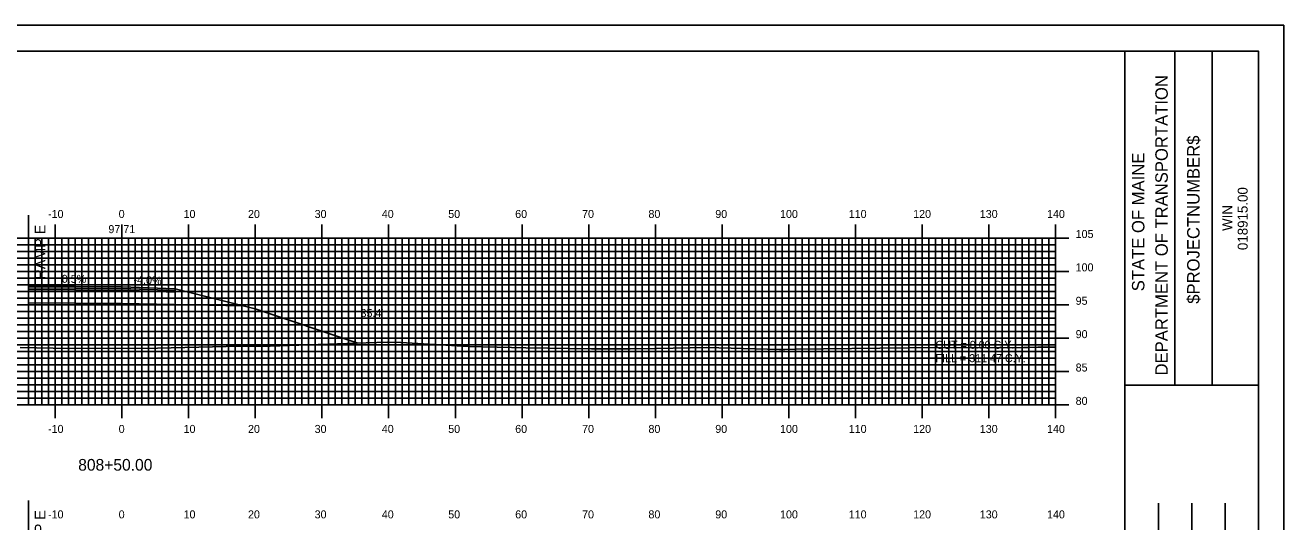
# Model space of a CAD drawing. Extents: x 1272 to 1616, y -1658 to -1438.
# Drawn here: x 1423.7 to 1612.4, y -1512.1 to -1437.7 of the extents above; entities that cross this region are included whole.
import ezdxf

# ---------------------------------------------------------------- set-up
doc = ezdxf.new("R2010")
doc.units = 0
for name, color, linetype in [('ANNOTATION', 7, 'Continuous'), ('BORDER', 7, 'Continuous'), ('D_Roadway_Centerline_Text', 7, 'Continuous'), ('D_Roadway_Edge_Shoulder', 7, 'Continuous'), ('D_Roadway_Edge_TW', 7, 'Continuous'), ('D_Roadway_Pavement', 7, 'Continuous'), ('D_Roadway_SlopeLines', 7, 'Continuous'), ('D_Roadway_SubGrade', 7, 'Continuous'), ('D_Text_Standard', 7, 'Continuous'), ('H_V ANNOTATION', 7, 'Continuous'), ('MAJOR', 7, 'Continuous'), ('MINOR', 7, 'Continuous'), ('PLOT BOUNDARY', 7, 'Continuous'), ('S_Roadway_Centerline', 7, 'Continuous')]:
    doc.layers.add(name, color=color, linetype=linetype)

msp = doc.modelspace()

# ---------------------------------------------------------------- linework, layer by layer
at = {"layer": 'BORDER'}
for p, q in [((1588.56, -1651.6), (1588.56, -1441.6)), ((1596.02, -1491.61), (1596.02, -1441.61)), ((1601.61, -1491.61), (1601.61, -1441.61)), ((1588.56, -1491.62), (1608.56, -1491.62)), ((1593.56, -1526.6), (1593.56, -1509.3)), ((1598.56, -1526.6), (1598.56, -1509.3)), ((1603.56, -1526.6), (1603.56, -1509.3))]:
    msp.add_line(p, q, dxfattribs=at)
msp.add_lwpolyline([(1288.56, -1651.6), (1608.56, -1651.6), (1608.56, -1441.6), (1288.56, -1441.6)], close=True, dxfattribs=at)
at = {"layer": 'D_Roadway_Edge_Shoulder'}
for points in [[(1438.16, -1476.89), (1446.16, -1477.21), (1446.16, -1477.46), (1438.16, -1477.14)], [(1438.16, -1477.14), (1446.16, -1477.46), (1446.16, -1477.71), (1438.16, -1477.39)]]:
    msp.add_lwpolyline(points, close=True, dxfattribs=at)
at = {"layer": 'D_Roadway_Edge_TW'}
msp.add_lwpolyline([(1424.16, -1476.83), (1438.16, -1476.89), (1438.16, -1477.14), (1424.16, -1477.08)], close=True, dxfattribs=at)
at = {"layer": 'D_Roadway_Pavement'}
msp.add_lwpolyline([(1424.16, -1477.08), (1438.16, -1477.14), (1438.16, -1477.39), (1424.16, -1477.33)], close=True, dxfattribs=at)
msp.add_lwpolyline([(1438.16, -1477.14), (1438.16, -1477.39)], dxfattribs=at)
msp.add_lwpolyline([(1438.16, -1477.14), (1438.16, -1477.39)], dxfattribs=at)
msp.add_lwpolyline([(1438.16, -1477.14), (1438.16, -1477.39)], dxfattribs=at)
at = {"layer": 'D_Roadway_SlopeLines'}
msp.add_lwpolyline([(1446.16, -1477.21), (1458.16, -1480.21), (1473.54, -1485.34)], dxfattribs=at)
at = {"layer": 'D_Roadway_SubGrade'}
for p, q in [((1424.16, -1466.19), (1424.16, -1479.33)), ((1424.16, -1508.94), (1424.16, -1522.08))]:
    msp.add_line(p, q, dxfattribs=at)
for points in [[(1424.16, -1477.33), (1438.16, -1477.39), (1438.16, -1479.39), (1424.16, -1479.33)], [(1438.16, -1477.39), (1438.16, -1477.14), (1446.16, -1477.46), (1446.16, -1477.21), (1456.33, -1479.75), (1438.16, -1479.39)]]:
    msp.add_lwpolyline(points, close=True, dxfattribs=at)
at = {"layer": 'MAJOR'}
for p, q in [((1428.16, -1467.6), (1428.16, -1469.6)), ((1438.16, -1467.6), (1438.16, -1469.6)), ((1448.16, -1467.6), (1448.16, -1469.6)), ((1458.16, -1467.6), (1458.16, -1469.6)), ((1468.16, -1467.6), (1468.16, -1469.6)), ((1478.16, -1467.6), (1478.16, -1469.6)), ((1488.16, -1467.6), (1488.16, -1469.6)), ((1498.16, -1467.6), (1498.16, -1469.6)), ((1508.16, -1467.6), (1508.16, -1469.6)), ((1518.16, -1467.6), (1518.16, -1469.6)), ((1528.16, -1467.6), (1528.16, -1469.6)), ((1538.16, -1467.6), (1538.16, -1469.6)), ((1548.16, -1467.6), (1548.16, -1469.6)), ((1558.16, -1467.6), (1558.16, -1469.6)), ((1568.16, -1467.6), (1568.16, -1469.6)), ((1578.16, -1467.6), (1578.16, -1469.6)), ((1298.16, -1469.6), (1578.16, -1469.6)), ((1298.16, -1469.6), (1578.16, -1469.6)), ((1428.16, -1494.6), (1428.16, -1469.6)), ((1438.16, -1494.6), (1438.16, -1469.6)), ((1448.16, -1494.6), (1448.16, -1469.6)), ((1458.16, -1494.6), (1458.16, -1469.6)), ((1468.16, -1494.6), (1468.16, -1469.6)), ((1478.16, -1494.6), (1478.16, -1469.6)), ((1488.16, -1494.6), (1488.16, -1469.6)), ((1498.16, -1494.6), (1498.16, -1469.6)), ((1508.16, -1494.6), (1508.16, -1469.6)), ((1518.16, -1494.6), (1518.16, -1469.6)), ((1528.16, -1494.6), (1528.16, -1469.6)), ((1538.16, -1494.6), (1538.16, -1469.6)), ((1548.16, -1494.6), (1548.16, -1469.6)), ((1558.16, -1494.6), (1558.16, -1469.6)), ((1568.16, -1494.6), (1568.16, -1469.6)), ((1580.16, -1469.6), (1576.16, -1469.6)), ((1578.16, -1494.6), (1578.16, -1469.6)), ((1578.16, -1494.6), (1578.16, -1469.6)), ((1298.16, -1474.6), (1578.16, -1474.6)), ((1580.16, -1474.6), (1576.16, -1474.6)), ((1298.16, -1479.6), (1578.16, -1479.6)), ((1580.16, -1479.6), (1576.16, -1479.6)), ((1298.16, -1484.6), (1578.16, -1484.6)), ((1580.16, -1484.6), (1576.16, -1484.6)), ((1298.16, -1489.6), (1578.16, -1489.6)), ((1580.16, -1489.6), (1576.16, -1489.6)), ((1298.16, -1494.6), (1578.16, -1494.6)), ((1298.16, -1494.6), (1578.16, -1494.6)), ((1428.16, -1496.61), (1428.16, -1494.6)), ((1438.16, -1496.61), (1438.16, -1494.6)), ((1448.16, -1496.61), (1448.16, -1494.6)), ((1458.16, -1496.61), (1458.16, -1494.6)), ((1468.16, -1496.61), (1468.16, -1494.6)), ((1478.16, -1496.61), (1478.16, -1494.6)), ((1488.16, -1496.61), (1488.16, -1494.6)), ((1498.16, -1496.61), (1498.16, -1494.6)), ((1508.16, -1496.61), (1508.16, -1494.6)), ((1518.16, -1496.61), (1518.16, -1494.6)), ((1528.16, -1496.61), (1528.16, -1494.6)), ((1538.16, -1496.61), (1538.16, -1494.6)), ((1548.16, -1496.61), (1548.16, -1494.6)), ((1558.16, -1496.61), (1558.16, -1494.6)), ((1568.16, -1496.61), (1568.16, -1494.6)), ((1580.16, -1494.6), (1576.16, -1494.6)), ((1578.16, -1496.61), (1578.16, -1494.6))]:
    msp.add_line(p, q, dxfattribs=at)
at = {"layer": 'MINOR'}
for p, q in [((1424.16, -1494.6), (1424.16, -1469.6)), ((1425.16, -1494.6), (1425.16, -1469.6)), ((1426.16, -1494.6), (1426.16, -1469.6)), ((1427.16, -1494.6), (1427.16, -1469.6)), ((1429.16, -1494.6), (1429.16, -1469.6)), ((1430.16, -1494.6), (1430.16, -1469.6)), ((1431.16, -1494.6), (1431.16, -1469.6)), ((1432.16, -1494.6), (1432.16, -1469.6)), ((1433.16, -1494.6), (1433.16, -1469.6)), ((1434.16, -1494.6), (1434.16, -1469.6)), ((1435.16, -1494.6), (1435.16, -1469.6)), ((1436.16, -1494.6), (1436.16, -1469.6)), ((1437.16, -1494.6), (1437.16, -1469.6)), ((1439.16, -1494.6), (1439.16, -1469.6)), ((1440.16, -1494.6), (1440.16, -1469.6)), ((1441.16, -1494.6), (1441.16, -1469.6)), ((1442.16, -1494.6), (1442.16, -1469.6)), ((1443.16, -1494.6), (1443.16, -1469.6)), ((1444.16, -1494.6), (1444.16, -1469.6)), ((1445.16, -1494.6), (1445.16, -1469.6)), ((1446.16, -1494.6), (1446.16, -1469.6)), ((1447.16, -1494.6), (1447.16, -1469.6)), ((1449.16, -1494.6), (1449.16, -1469.6)), ((1450.16, -1494.6), (1450.16, -1469.6)), ((1451.16, -1494.6), (1451.16, -1469.6)), ((1452.16, -1494.6), (1452.16, -1469.6)), ((1453.16, -1494.6), (1453.16, -1469.6)), ((1454.16, -1494.6), (1454.16, -1469.6)), ((1455.16, -1494.6), (1455.16, -1469.6)), ((1456.16, -1494.6), (1456.16, -1469.6)), ((1457.16, -1494.6), (1457.16, -1469.6)), ((1459.16, -1494.6), (1459.16, -1469.6)), ((1460.16, -1494.6), (1460.16, -1469.6)), ((1461.16, -1494.6), (1461.16, -1469.6)), ((1462.16, -1494.6), (1462.16, -1469.6)), ((1463.16, -1494.6), (1463.16, -1469.6)), ((1464.16, -1494.6), (1464.16, -1469.6)), ((1465.16, -1494.6), (1465.16, -1469.6)), ((1466.16, -1494.6), (1466.16, -1469.6)), ((1467.16, -1494.6), (1467.16, -1469.6)), ((1469.16, -1494.6), (1469.16, -1469.6)), ((1470.16, -1494.6), (1470.16, -1469.6)), ((1471.16, -1494.6), (1471.16, -1469.6)), ((1472.16, -1494.6), (1472.16, -1469.6)), ((1473.16, -1494.6), (1473.16, -1469.6)), ((1474.16, -1494.6), (1474.16, -1469.6)), ((1475.16, -1494.6), (1475.16, -1469.6)), ((1476.16, -1494.6), (1476.16, -1469.6)), ((1477.16, -1494.6), (1477.16, -1469.6)), ((1479.16, -1494.6), (1479.16, -1469.6)), ((1480.16, -1494.6), (1480.16, -1469.6)), ((1481.16, -1494.6), (1481.16, -1469.6)), ((1482.16, -1494.6), (1482.16, -1469.6)), ((1483.16, -1494.6), (1483.16, -1469.6)), ((1484.16, -1494.6), (1484.16, -1469.6)), ((1485.16, -1494.6), (1485.16, -1469.6)), ((1486.16, -1494.6), (1486.16, -1469.6)), ((1487.16, -1494.6), (1487.16, -1469.6)), ((1489.16, -1494.6), (1489.16, -1469.6)), ((1490.16, -1494.6), (1490.16, -1469.6)), ((1491.16, -1494.6), (1491.16, -1469.6)), ((1492.16, -1494.6), (1492.16, -1469.6)), ((1493.16, -1494.6), (1493.16, -1469.6)), ((1494.16, -1494.6), (1494.16, -1469.6)), ((1495.16, -1494.6), (1495.16, -1469.6)), ((1496.16, -1494.6), (1496.16, -1469.6)), ((1497.16, -1494.6), (1497.16, -1469.6)), ((1499.16, -1494.6), (1499.16, -1469.6)), ((1500.16, -1494.6), (1500.16, -1469.6)), ((1501.16, -1494.6), (1501.16, -1469.6)), ((1502.16, -1494.6), (1502.16, -1469.6)), ((1503.16, -1494.6), (1503.16, -1469.6)), ((1504.16, -1494.6), (1504.16, -1469.6)), ((1505.16, -1494.6), (1505.16, -1469.6)), ((1506.16, -1494.6), (1506.16, -1469.6)), ((1507.16, -1494.6), (1507.16, -1469.6)), ((1509.16, -1494.6), (1509.16, -1469.6)), ((1510.16, -1494.6), (1510.16, -1469.6)), ((1511.16, -1494.6), (1511.16, -1469.6)), ((1512.16, -1494.6), (1512.16, -1469.6)), ((1513.16, -1494.6), (1513.16, -1469.6)), ((1514.16, -1494.6), (1514.16, -1469.6)), ((1515.16, -1494.6), (1515.16, -1469.6)), ((1516.16, -1494.6), (1516.16, -1469.6)), ((1517.16, -1494.6), (1517.16, -1469.6)), ((1519.16, -1494.6), (1519.16, -1469.6)), ((1520.16, -1494.6), (1520.16, -1469.6)), ((1521.16, -1494.6), (1521.16, -1469.6)), ((1522.16, -1494.6), (1522.16, -1469.6)), ((1523.16, -1494.6), (1523.16, -1469.6)), ((1524.16, -1494.6), (1524.16, -1469.6)), ((1525.16, -1494.6), (1525.16, -1469.6)), ((1526.16, -1494.6), (1526.16, -1469.6)), ((1527.16, -1494.6), (1527.16, -1469.6)), ((1529.16, -1494.6), (1529.16, -1469.6)), ((1530.16, -1494.6), (1530.16, -1469.6)), ((1531.16, -1494.6), (1531.16, -1469.6)), ((1532.16, -1494.6), (1532.16, -1469.6)), ((1533.16, -1494.6), (1533.16, -1469.6)), ((1534.16, -1494.6), (1534.16, -1469.6)), ((1535.16, -1494.6), (1535.16, -1469.6)), ((1536.16, -1494.6), (1536.16, -1469.6)), ((1537.16, -1494.6), (1537.16, -1469.6)), ((1539.16, -1494.6), (1539.16, -1469.6)), ((1540.16, -1494.6), (1540.16, -1469.6)), ((1541.16, -1494.6), (1541.16, -1469.6)), ((1542.16, -1494.6), (1542.16, -1469.6)), ((1543.16, -1494.6), (1543.16, -1469.6)), ((1544.16, -1494.6), (1544.16, -1469.6)), ((1545.16, -1494.6), (1545.16, -1469.6)), ((1546.16, -1494.6), (1546.16, -1469.6)), ((1547.16, -1494.6), (1547.16, -1469.6)), ((1549.16, -1494.6), (1549.16, -1469.6)), ((1550.16, -1494.6), (1550.16, -1469.6)), ((1551.16, -1494.6), (1551.16, -1469.6)), ((1552.16, -1494.6), (1552.16, -1469.6)), ((1553.16, -1494.6), (1553.16, -1469.6)), ((1554.16, -1494.6), (1554.16, -1469.6)), ((1555.16, -1494.6), (1555.16, -1469.6)), ((1556.16, -1494.6), (1556.16, -1469.6)), ((1557.16, -1494.6), (1557.16, -1469.6)), ((1559.16, -1494.6), (1559.16, -1469.6)), ((1560.16, -1494.6), (1560.16, -1469.6)), ((1561.16, -1494.6), (1561.16, -1469.6)), ((1562.16, -1494.6), (1562.16, -1469.6)), ((1563.16, -1494.6), (1563.16, -1469.6)), ((1564.16, -1494.6), (1564.16, -1469.6)), ((1565.16, -1494.6), (1565.16, -1469.6)), ((1566.16, -1494.6), (1566.16, -1469.6)), ((1567.16, -1494.6), (1567.16, -1469.6)), ((1569.16, -1494.6), (1569.16, -1469.6)), ((1570.16, -1494.6), (1570.16, -1469.6)), ((1571.16, -1494.6), (1571.16, -1469.6)), ((1572.16, -1494.6), (1572.16, -1469.6)), ((1573.16, -1494.6), (1573.16, -1469.6)), ((1574.16, -1494.6), (1574.16, -1469.6)), ((1575.16, -1494.6), (1575.16, -1469.6)), ((1576.16, -1494.6), (1576.16, -1469.6)), ((1577.16, -1494.6), (1577.16, -1469.6)), ((1298.16, -1470.6), (1578.16, -1470.6)), ((1298.16, -1471.6), (1578.16, -1471.6)), ((1578.16, -1470.6), (1576.16, -1470.6)), ((1578.16, -1471.6), (1576.16, -1471.6)), ((1298.16, -1472.6), (1578.16, -1472.6)), ((1298.16, -1473.6), (1578.16, -1473.6)), ((1578.16, -1472.6), (1576.16, -1472.6)), ((1578.16, -1473.6), (1576.16, -1473.6)), ((1298.16, -1475.6), (1578.16, -1475.6)), ((1578.16, -1475.6), (1576.16, -1475.6)), ((1298.16, -1476.6), (1578.16, -1476.6)), ((1298.16, -1477.6), (1578.16, -1477.6)), ((1578.16, -1476.6), (1576.16, -1476.6)), ((1578.16, -1477.6), (1576.16, -1477.6)), ((1298.16, -1478.6), (1578.16, -1478.6)), ((1578.16, -1478.6), (1576.16, -1478.6)), ((1298.16, -1480.6), (1578.16, -1480.6)), ((1578.16, -1480.6), (1576.16, -1480.6)), ((1298.16, -1481.6), (1578.16, -1481.6)), ((1298.16, -1482.6), (1578.16, -1482.6)), ((1578.16, -1481.6), (1576.16, -1481.6)), ((1578.16, -1482.6), (1576.16, -1482.6)), ((1298.16, -1483.6), (1578.16, -1483.6)), ((1578.16, -1483.6), (1576.16, -1483.6)), ((1298.16, -1485.6), (1578.16, -1485.6)), ((1298.16, -1486.6), (1578.16, -1486.6)), ((1578.16, -1485.6), (1576.16, -1485.6)), ((1578.16, -1486.6), (1576.16, -1486.6)), ((1298.16, -1487.6), (1578.16, -1487.6)), ((1298.16, -1488.6), (1578.16, -1488.6)), ((1578.16, -1487.6), (1576.16, -1487.6)), ((1578.16, -1488.6), (1576.16, -1488.6)), ((1298.16, -1490.6), (1578.16, -1490.6)), ((1578.16, -1490.6), (1576.16, -1490.6)), ((1298.16, -1491.6), (1578.16, -1491.6)), ((1298.16, -1492.6), (1578.16, -1492.6)), ((1578.16, -1491.6), (1576.16, -1491.6)), ((1578.16, -1492.6), (1576.16, -1492.6)), ((1298.16, -1493.6), (1578.16, -1493.6)), ((1578.16, -1493.6), (1576.16, -1493.6))]:
    msp.add_line(p, q, dxfattribs=at)
at = {"layer": 'PLOT BOUNDARY'}
msp.add_lwpolyline([(1272.37, -1657.72), (1612.37, -1657.72), (1612.37, -1437.72), (1272.37, -1437.72)], close=True, dxfattribs=at)
at = {"layer": 'S_Roadway_Centerline'}
msp.add_lwpolyline([(1422.9, -1486), (1430.31, -1486.16), (1443.48, -1486.09), (1453.78, -1485.86), (1460.38, -1485.8), (1474.77, -1485.29), (1478, -1485.19), (1479.99, -1485.24), (1490.11, -1485.84), (1498.75, -1486.06), (1508.59, -1486.21), (1514.39, -1486.22), (1518.32, -1486.17), (1525.85, -1485.99), (1536.75, -1486.29), (1537.58, -1486.28), (1539.13, -1486.25), (1556.03, -1486.06), (1573.33, -1485.98), (1573.84, -1485.98), (1574.09, -1485.98), (1575.48, -1485.96), (1578.16, -1485.94)], dxfattribs=at)

# ---------------------------------------------------------------- texts
at = {"layer": 'ANNOTATION'}
for s, height, rotation, p in [('RAMP E', 1.6, 90, (1426.69, -1475.82)), ('0.5%', 1.2, 359.7335, (1429.15, -1476.31)), ('-4.0%', 1.2, 357.7094, (1439.89, -1476.43)), ('RAMP E', 1.6, 90, (1426.69, -1518.57))]:
    msp.add_text(s, height=height, rotation=rotation, dxfattribs=at).set_placement(p)
at = {"layer": 'BORDER'}
for s, height, p in [('DEPARTMENT OF TRANSPORTATION', 1.8635, (1594.97, -1490.19)), ('$PROJECTNUMBER$', 1.8635, (1599.74, -1479.45)), ('STATE OF MAINE', 1.8635, (1591.47, -1477.58)), ('018915.00', 1.491, (1606.95, -1471.41)), ('WIN', 1.491, (1604.63, -1468.54))]:
    msp.add_text(s, height=height, rotation=90, dxfattribs=at).set_placement(p)
at = {"layer": 'D_Roadway_Centerline_Text'}
msp.add_text('97.71', height=1.2, dxfattribs=at).set_placement((1436.14, -1468.87))
at = {"layer": 'D_Text_Standard'}
for s, p in [("35.4'", (1473.94, -1481.44)), ('CUT = 0.00 C.Y.', (1560.16, -1486.2)), ('FILL = 311.47 C.Y.', (1560.16, -1488.2))]:
    msp.add_text(s, height=1.2, dxfattribs=at).set_placement(p)
at = {"layer": 'H_V ANNOTATION'}
for s, height, p in [('-10', 1.2, (1427.09, -1466.6)), ('0', 1.2, (1437.68, -1466.6)), ('10', 1.2, (1447.41, -1466.6)), ('20', 1.2, (1457.07, -1466.6)), ('30', 1.2, (1467.06, -1466.6)), ('40', 1.2, (1477.13, -1466.6)), ('50', 1.2, (1487.09, -1466.6)), ('60', 1.2, (1497.13, -1466.6)), ('70', 1.2, (1507.16, -1466.6)), ('80', 1.2, (1517.11, -1466.6)), ('90', 1.2, (1527.13, -1466.6)), ('100', 1.2, (1536.84, -1466.6)), ('110', 1.2, (1547.14, -1466.6)), ('120', 1.2, (1556.8, -1466.6)), ('130', 1.2, (1566.79, -1466.6)), ('140', 1.2, (1576.87, -1466.6)), ('105', 1.2, (1581.16, -1469.6)), ('100', 1.2, (1581.16, -1474.6)), ('95', 1.2, (1581.16, -1479.6)), ('90', 1.2, (1581.16, -1484.6)), ('85', 1.2, (1581.16, -1489.6)), ('80', 1.2, (1581.16, -1494.6)), ('-10', 1.2, (1427.09, -1498.8)), ('0', 1.2, (1437.68, -1498.8)), ('10', 1.2, (1447.41, -1498.8)), ('20', 1.2, (1457.07, -1498.8)), ('30', 1.2, (1467.06, -1498.8)), ('40', 1.2, (1477.13, -1498.8)), ('50', 1.2, (1487.09, -1498.8)), ('60', 1.2, (1497.13, -1498.8)), ('70', 1.2, (1507.16, -1498.8)), ('80', 1.2, (1517.11, -1498.8)), ('90', 1.2, (1527.13, -1498.8)), ('100', 1.2, (1536.84, -1498.8)), ('110', 1.2, (1547.14, -1498.8)), ('120', 1.2, (1556.8, -1498.8)), ('130', 1.2, (1566.79, -1498.8)), ('140', 1.2, (1576.87, -1498.8)), ('808+50.00', 1.75, (1431.61, -1504.45)), ('-10', 1.2, (1427.09, -1511.6)), ('0', 1.2, (1437.68, -1511.6)), ('10', 1.2, (1447.41, -1511.6)), ('20', 1.2, (1457.07, -1511.6)), ('30', 1.2, (1467.06, -1511.6)), ('40', 1.2, (1477.13, -1511.6)), ('50', 1.2, (1487.09, -1511.6)), ('60', 1.2, (1497.13, -1511.6)), ('70', 1.2, (1507.16, -1511.6)), ('80', 1.2, (1517.11, -1511.6)), ('90', 1.2, (1527.13, -1511.6)), ('100', 1.2, (1536.84, -1511.6)), ('110', 1.2, (1547.14, -1511.6)), ('120', 1.2, (1556.8, -1511.6)), ('130', 1.2, (1566.79, -1511.6)), ('140', 1.2, (1576.87, -1511.6))]:
    msp.add_text(s, height=height, dxfattribs=at).set_placement(p)

doc.saveas('drawing.dxf')
